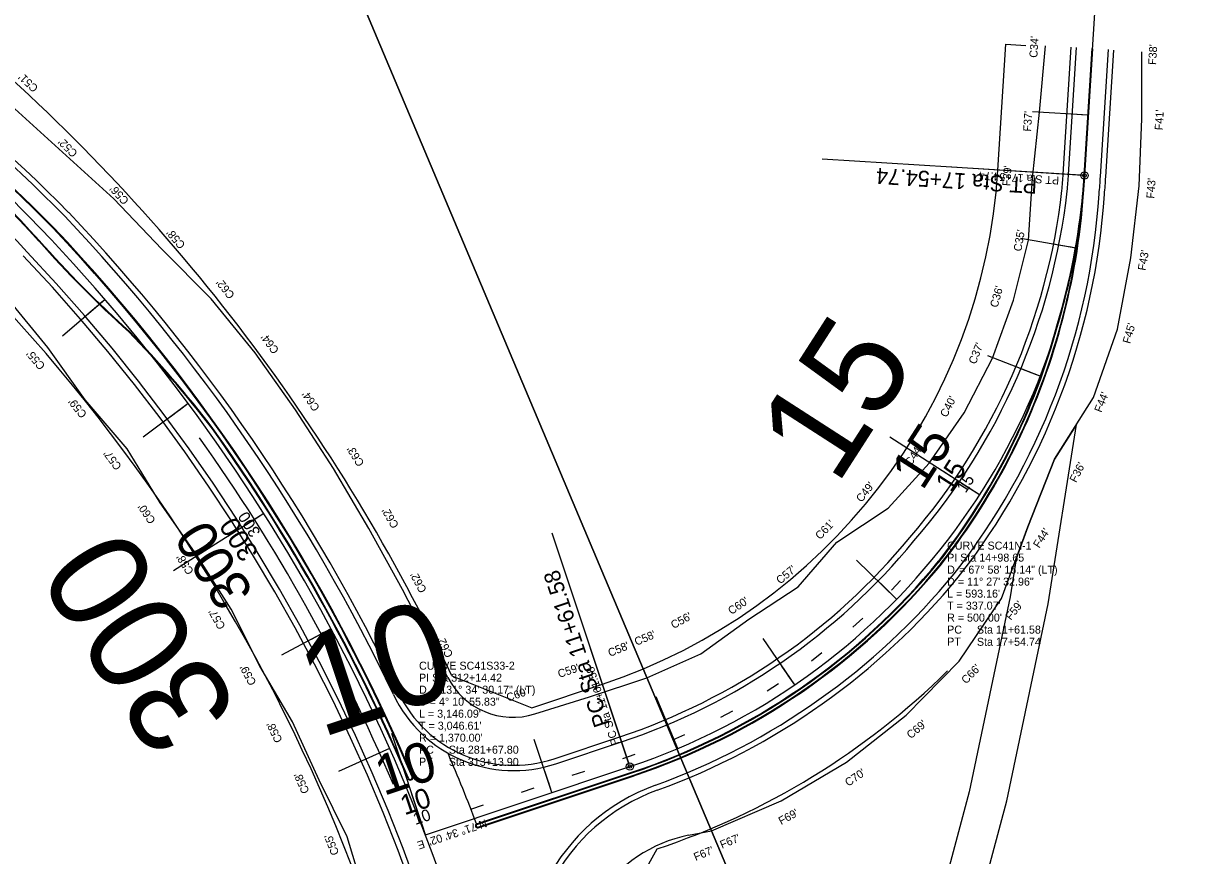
# Model space of a CAD drawing. Extents: x 2358865 to 2362945, y 393485 to 404880.
# Drawn here: x 2361585 to 2362454, y 401432 to 402057 of the extents above; entities that cross this region are included whole.
import ezdxf

# ---------------------------------------------------------------- set-up
doc = ezdxf.new("R2010")
doc.units = 0
for name, color, linetype in [('CL', 7, 'Continuous'), ('Level 11', 7, 'Continuous'), ('Level 19', 7, 'Continuous'), ('Level 21', 7, 'Continuous'), ('Level 22', 7, 'Continuous'), ('Level 25', 7, 'Continuous'), ('Level 27', 7, 'Continuous'), ('Level 28', 7, 'Continuous'), ('Level 30', 7, 'Continuous'), ('Level 33', 7, 'Continuous'), ('Level 35', 7, 'Continuous'), ('Level 36', 7, 'Continuous'), ('Level 37', 7, 'Continuous'), ('Level 39', 7, 'Continuous'), ('Level 41', 7, 'Continuous'), ('Level 48', 7, 'Continuous'), ('Level 50', 7, 'Continuous'), ('Level 51', 7, 'Continuous'), ('Level 52', 7, 'Continuous'), ('Level 53', 7, 'Continuous'), ('Level 61', 7, 'Continuous'), ('Level 63', 7, 'Continuous')]:
    doc.layers.add(name, color=color, linetype=linetype)

msp = doc.modelspace()

# ---------------------------------------------------------------- linework, layer by layer
at = {"layer": 'CL'}
for p, q in [((2362381, 401942.38), (2362564.78, 404866.59)), ((2361886.79, 401448.3), (2362040.08, 401499.39))]:
    msp.add_line(p, q, dxfattribs=at)
for centre, radius, start, end in [((2360608.55, 400955.34), 1370, 315.75191, 87.32696), ((2361881.98, 401973.74), 500, 288.43269, 356.40384)]:
    msp.add_arc(centre, radius, start, end, dxfattribs=at)
at = {"layer": 'Level 11'}
for p, q in [((2362365.03, 401943.38), (2362371.01, 402038.45)), ((2362396.97, 401941.37), (2362402.94, 402036.45)), ((2361983.42, 401505.28), (2362032.65, 401521.68))]:
    msp.add_line(p, q, dxfattribs=at)
for centre, radius, start, end in [((2360631.17, 400937.8), 1389.46, 44.67453, 59.73673), ((2361881.98, 401973.74), 484, 354.94405, 356.40384), ((2361881.98, 401973.74), 516, 354.94405, 356.40384), ((2361887.08, 401985.35), 480.09, 319.11516, 353.52136), ((2361877.46, 401961.88), 519.6, 321.89792, 356.30055), ((2360608.55, 400955.34), 1393.5, 25.49016, 43.50459), ((2360608.55, 400955.34), 1346.5, 319.72072, 43.50459), ((2361881.98, 401973.74), 476.5, 288.43269, 320.57265), ((2361881.98, 401973.74), 523.5, 289.95493, 320.57169), ((2361953.07, 401596.35), 96, 205.49016, 288.43269), ((2362110.47, 401344.43), 146, 109.95493, 194.52415)]:
    msp.add_arc(centre, radius, start, end, dxfattribs=at)
at = {"layer": 'Level 19'}
for p, q in [((2362369.02, 401943.13), (2362375, 402038.2)), ((2362392.98, 401941.62), (2362398.95, 402036.7)), ((2361984.68, 401501.48), (2362033.91, 401517.89))]:
    msp.add_line(p, q, dxfattribs=at)
for centre, radius, start, end in [((2360631.17, 400937.8), 1385.46, 44.67453, 59.73673), ((2360586.69, 400973.8), 1353.95, 42.30084, 57.36334), ((2361881.98, 401973.74), 488, 354.94405, 356.40384), ((2361881.98, 401973.74), 512, 354.94405, 356.40384), ((2361887.08, 401985.35), 484.09, 319.12118, 353.52136), ((2361877.46, 401961.88), 515.6, 321.90306, 356.30055), ((2360608.55, 400955.34), 1389.5, 25.49016, 43.50459), ((2360608.55, 400955.34), 1350.5, 319.72072, 43.50459), ((2361881.98, 401973.74), 480.5, 288.43269, 320.56658), ((2361881.98, 401973.74), 519.5, 289.95493, 320.56658), ((2361953.07, 401596.35), 100, 205.49016, 288.43269), ((2362110.47, 401344.43), 150, 109.95493, 194.52415)]:
    msp.add_arc(centre, radius, start, end, dxfattribs=at)
at = {"layer": 'Level 25'}
for p, q in [((2362383.84, 401987.55), (2362378.85, 401987.86)), ((2362374.59, 401888.04), (2362369.66, 401888.9)), ((2361646.55, 401849.47), (2361642.76, 401846.21)), ((2362347.74, 401791.88), (2362343.08, 401793.7)), ((2361708.99, 401771.39), (2361704.97, 401768.41)), ((2362302.33, 401702.98), (2362295.6, 401707.31)), ((2361765.57, 401688.96), (2361758.82, 401684.68)), ((2362240.16, 401624.87), (2362236.58, 401628.35)), ((2361815.99, 401602.63), (2361811.59, 401600.27)), ((2362163.71, 401560.66), (2362160.89, 401564.79)), ((2362076.03, 401512.93), (2362074.09, 401517.53)), ((2361859.98, 401512.85), (2361855.42, 401510.82)), ((2361981.66, 401479.92), (2361980.08, 401484.66)), ((2361886.79, 401448.3), (2361884.26, 401455.89))]:
    msp.add_line(p, q, dxfattribs=at)
at = {"layer": 'Level 27'}
for p, q in [((2362316.13, 401946.45), (2362322.06, 402040.82)), ((2362322.06, 402040.82), (2362337.03, 402039.87)), ((2361906.52, 401567.32), (2361966.52, 401543.39)), ((2361966.52, 401543.39), (2362019.53, 401561.05)), ((2362002.99, 401334.23), (2362060.53, 401437.69)), ((2362060.53, 401437.69), (2362060.63, 401437.72))]:
    msp.add_line(p, q, dxfattribs=at)
for centre, radius, start, end in [((2360608.55, 400955.34), 1310, 18.31889, 61.65271), ((2360608.55, 400955.34), 1435, 25.24354, 49.10619), ((2361881.98, 401973.74), 435, 288.43269, 356.40384), ((2361881.98, 401973.74), 565, 288.43269, 314.55429)]:
    msp.add_arc(centre, radius, start, end, dxfattribs=at)
at = {"layer": 'Level 28'}
for p, q in [((2362379.75, 401942.45), (2362281.47, 401948.63)), ((2362039.68, 401500.58), (2362010.58, 401587.89))]:
    msp.add_line(p, q, dxfattribs=at)
for centre in [(2362381, 401942.38), (2362040.08, 401499.39)]:
    msp.add_circle(centre, 1.25, dxfattribs=at)
at = {"layer": 'Level 30'}
for p, q in [((2362383.84, 401987.55), (2362375.36, 401988.08)), ((2362374.59, 401888.04), (2362366.21, 401889.5)), ((2361646.55, 401849.47), (2361640.11, 401843.92)), ((2362347.74, 401791.88), (2362339.82, 401794.98)), ((2361708.99, 401771.39), (2361702.16, 401766.33)), ((2362302.33, 401702.98), (2362288.88, 401711.64)), ((2361765.57, 401688.96), (2361752.06, 401680.4)), ((2362240.16, 401624.87), (2362234.07, 401630.8)), ((2361815.99, 401602.63), (2361808.5, 401598.62)), ((2362163.71, 401560.66), (2362158.92, 401567.68)), ((2362076.03, 401512.93), (2362072.73, 401520.76)), ((2361859.98, 401512.85), (2361852.22, 401509.39)), ((2361981.66, 401479.92), (2361978.97, 401487.98)), ((2361886.79, 401448.3), (2361881.73, 401463.48))]:
    msp.add_line(p, q, dxfattribs=at)
at = {"layer": 'Level 33'}
for p, q in [((2362378.3, 401942.55), (2362184.24, 401954.74)), ((2362039.23, 401501.95), (2361981.81, 401674.21))]:
    msp.add_line(p, q, dxfattribs=at)
for centre in [(2362381, 401942.38), (2362040.08, 401499.39)]:
    msp.add_circle(centre, 2.7, dxfattribs=at)
at = {"layer": 'Level 35'}
msp.add_arc((2360618.78, 400958.7), 1398, 20.85338, 23.1961, dxfattribs=at)
at = {"layer": 'Level 36'}
for p, q in [((2362236.18, 401631.54), (2362243.06, 401638.8)), ((2362207.25, 401603.93), (2362214.7, 401610.61)), ((2362176.18, 401578.76), (2362184.14, 401584.82)), ((2362143.17, 401556.2), (2362151.59, 401561.59)), ((2362108.43, 401536.38), (2362117.26, 401541.07)), ((2362072.2, 401519.45), (2362081.39, 401523.41)), ((2362034.72, 401505.51), (2362044.19, 401508.72)), ((2361996.77, 401492.86), (2362006.26, 401496.02)), ((2361958.83, 401480.21), (2361968.31, 401483.38)), ((2361920.88, 401467.57), (2361930.37, 401470.73))]:
    msp.add_line(p, q, dxfattribs=at)
msp.add_arc((2360608.01, 400954.78), 1362.5, 22.94087, 35.48747, dxfattribs=at)
at = {"layer": 'Level 37'}
for p, q in [((2362380.75, 401942.39), (2362386.72, 402037.46)), ((2362381.25, 401942.36), (2362387.22, 402037.43)), ((2361925.2, 401456.36), (2362041.5, 401495.12)), ((2361925.36, 401455.89), (2362041.66, 401494.65)), ((2361926.11, 401454.03), (2362042.29, 401492.75)), ((2361926.27, 401453.55), (2362042.45, 401492.27))]:
    msp.add_line(p, q, dxfattribs=at)
for centre, radius, start, end in [((2360586.69, 400973.8), 1365.95, 42.30084, 56.86254), ((2360631.17, 400937.8), 1373.46, 44.67453, 59.2385), ((2360586.69, 400973.8), 1366.45, 42.30084, 56.3574), ((2360631.17, 400937.8), 1372.96, 44.67453, 58.73575), ((2361881.98, 401973.74), 499.75, 354.9005, 356.40384), ((2361881.98, 401973.74), 500.25, 354.9005, 356.40384), ((2361882.23, 401975.03), 499.62, 343.29164, 354.75087), ((2361880.12, 401962.68), 501.24, 344.7134, 356.17826), ((2361882.23, 401975.03), 500.12, 343.29164, 352.45531), ((2361880.12, 401962.68), 500.74, 344.7134, 353.88728), ((2360608.55, 400955.34), 1377, 22.92825, 43.50459), ((2360608.55, 400955.34), 1377.5, 22.92825, 43.50459), ((2362225.76, 402450.09), 840, 221.51699, 228.05535), ((2362225.76, 402450.09), 839.5, 221.51699, 228.05535), ((2361877.46, 401961.88), 500.6, 321.90306, 344.88936), ((2361877.46, 401961.88), 501.1, 321.90306, 344.88936), ((2361877.46, 401961.88), 503.1, 321.90306, 344.88073), ((2361877.46, 401961.88), 503.6, 321.90306, 344.88073), ((2361060.46, 401241.36), 840, 37.47579, 44.04044), ((2361060.46, 401241.36), 840.5, 37.47579, 44.04044), ((2360608.55, 400955.34), 1373.5, 22.92825, 35.47481), ((2360608.55, 400955.34), 1374, 22.92825, 35.47481), ((2361881.98, 401973.74), 504.5, 288.43269, 320.56658), ((2361881.98, 401973.74), 505, 288.43269, 320.56658), ((2361881.98, 401973.74), 507, 288.43269, 320.56658), ((2361881.98, 401973.74), 507.5, 288.43269, 320.56658), ((2361875.38, 401491.2), 2, 202.94087, 22.94087), ((2361875.38, 401491.2), 1.5, 202.94087, 22.94087), ((2361925.8, 401454.98), 1.5, 108.43269, 288.43269), ((2361925.8, 401454.98), 1, 108.43269, 288.43269)]:
    msp.add_arc(centre, radius, start, end, dxfattribs=at)
at = {"layer": 'Level 39'}
for p, q in [((2362383.84, 401987.55), (2362366.87, 401988.61)), ((2362374.59, 401888.04), (2362357.84, 401890.96)), ((2361646.55, 401849.47), (2361633.67, 401838.37)), ((2362347.74, 401791.88), (2362331.91, 401798.07)), ((2361708.99, 401771.39), (2361695.33, 401761.26)), ((2362302.33, 401702.98), (2362275.43, 401720.31)), ((2361765.57, 401688.96), (2361738.55, 401671.83)), ((2362240.16, 401624.87), (2362227.98, 401636.73)), ((2361815.99, 401602.63), (2361801.01, 401594.6)), ((2362163.71, 401560.66), (2362154.13, 401574.71)), ((2362076.03, 401512.93), (2362069.43, 401528.59)), ((2361859.98, 401512.85), (2361844.45, 401505.93)), ((2361981.66, 401479.92), (2361976.28, 401496.05)), ((2361886.79, 401448.3), (2361876.67, 401478.66))]:
    msp.add_line(p, q, dxfattribs=at)
at = {"layer": 'Level 41'}
for p, q in [((2362383.84, 401987.55), (2362341.92, 401990.18)), ((2362374.59, 401888.04), (2362333.21, 401895.24)), ((2361646.55, 401849.47), (2361614.72, 401822.06)), ((2362347.74, 401791.88), (2362308.62, 401807.16)), ((2361708.99, 401771.39), (2361675.25, 401746.37)), ((2362302.33, 401702.98), (2362235.07, 401746.3)), ((2361765.57, 401688.96), (2361698.01, 401646.12)), ((2362240.16, 401624.87), (2362210.07, 401654.17)), ((2361815.99, 401602.63), (2361778.98, 401582.79)), ((2362163.71, 401560.66), (2362140.04, 401595.36)), ((2362076.03, 401512.93), (2362059.73, 401551.63)), ((2361886.79, 401448.3), (2361861.49, 401524.2)), ((2361981.66, 401479.92), (2361968.38, 401519.76)), ((2361859.98, 401512.85), (2361821.62, 401495.76))]:
    msp.add_line(p, q, dxfattribs=at)
at = {"layer": 'Level 48'}
for centre, radius, start, end in [((2360631.17, 400937.8), 1372.96, 44.67986, 58.73575), ((2360586.69, 400973.8), 1366.45, 42.3191, 56.3574), ((2360608.55, 400955.34), 1377, 22.92827, 43.49928), ((2362225.76, 402450.09), 839.5, 221.504, 228.05655), ((2361060.46, 401241.36), 840.5, 37.4752, 44.04163), ((2360608.55, 400955.34), 1374, 22.92827, 35.47518), ((2361875.38, 401491.2), 1.5, 202.92827, 22.92827)]:
    msp.add_arc(centre, radius, start, end, dxfattribs=at)
at = {"layer": 'Level 50'}
for p, q in [((2361614.55, 401959.8), (2361576.27, 401994.85)), ((2361653.17, 401924.84), (2361614.55, 401959.8)), ((2361689.05, 401887.07), (2361653.17, 401924.84)), ((2362327.82, 401848.99), (2362339.03, 401894.04)), ((2361726.02, 401849.94), (2361689.05, 401887.07)), ((2361603.65, 401813.42), (2361573.29, 401850.7)), ((2361759.05, 401809.38), (2361726.02, 401849.94)), ((2362312.08, 401805.42), (2362327.82, 401848.99)), ((2361631.62, 401774.36), (2361603.65, 401813.42)), ((2361789.47, 401766.81), (2361759.05, 401809.38)), ((2362290.83, 401764.41), (2362312.08, 401805.42)), ((2361663.23, 401737.46), (2361631.62, 401774.36)), ((2361817.83, 401722.85), (2361789.47, 401766.81)), ((2362264.49, 401726.74), (2362290.83, 401764.41)), ((2361687.93, 401697.02), (2361663.23, 401737.46)), ((2362233.7, 401693.07), (2362264.49, 401726.74)), ((2361844.27, 401677.75), (2361817.83, 401722.85)), ((2361715.34, 401657.78), (2361687.93, 401697.02)), ((2362195.32, 401667.65), (2362233.7, 401693.07)), ((2361869.61, 401632.04), (2361844.27, 401677.75)), ((2362166.38, 401634.04), (2362195.32, 401667.65)), ((2361741.08, 401617.4), (2361715.34, 401657.78)), ((2361903.56, 401566.12), (2361869.61, 401632.04)), ((2362129.38, 401609.74), (2362166.38, 401634.04)), ((2361762.73, 401574.66), (2361741.08, 401617.4)), ((2362093.43, 401583.82), (2362129.38, 401609.74)), ((2362052.92, 401565.87), (2362093.43, 401583.82)), ((2362247.29, 401537.84), (2362287.02, 401578.45)), ((2361787.13, 401532.82), (2361762.73, 401574.66)), ((2362009.73, 401551.57), (2362052.92, 401565.87)), ((2361968.85, 401538.81), (2362009.73, 401551.57)), ((2362202.52, 401502.65), (2362247.29, 401537.84)), ((2361807.07, 401489.28), (2361787.13, 401532.82)), ((2361828.08, 401446.6), (2361807.07, 401489.28)), ((2361842.33, 401400.71), (2361828.08, 401446.6))]:
    msp.add_line(p, q, dxfattribs=at)
msp.add_arc((2361952.46, 401591.31), 55, 207.24943, 287.34074, dxfattribs=at)
at = {"layer": 'Level 51'}
for p, q in [((2362424.07, 401984.94), (2362424.08, 402035.04)), ((2362341.96, 401940.45), (2362347.35, 401989.84)), ((2362422.12, 401934.61), (2362424.07, 401984.94)), ((2362415.69, 401880.75), (2362422.12, 401934.61)), ((2362405.7, 401827.3), (2362415.69, 401880.75)), ((2362387.85, 401775.9), (2362405.7, 401827.3)), ((2362358.56, 401729.87), (2362387.85, 401775.9)), ((2362338.58, 401679.09), (2362358.56, 401729.87)), ((2362318.79, 401625.43), (2362338.58, 401679.09)), ((2362101.26, 401451.3), (2362153.49, 401473.68)), ((2362084.1, 401447.87), (2362101.26, 401451.3))]:
    msp.add_line(p, q, dxfattribs=at)
at = {"layer": 'Level 52'}
for p, q in [((2362347.35, 401989.84), (2362351.76, 402039.62)), ((2362339.03, 401894.04), (2362341.96, 401940.45)), ((2362287.02, 401578.45), (2362318.79, 401625.43)), ((2362153.49, 401473.68), (2362202.52, 401502.65))]:
    msp.add_line(p, q, dxfattribs=at)
msp.add_arc((2362104.67, 401344.91), 105, 101.29963, 192.42448, dxfattribs=at)
at = {"layer": 'Level 61'}
for p, q in [((2362353.8, 401621.34), (2362374.97, 401755.66)), ((2362374.97, 401755.66), (2362358.56, 401729.87)), ((2362358.56, 401729.87), (2362338.58, 401679.09)), ((2362338.58, 401679.09), (2362329.77, 401655.2)), ((2362329.77, 401655.2), (2362325.27, 401626.59)), ((2362325.27, 401626.59), (2362294.45, 401480.49)), ((2362322.67, 401473.76), (2362353.8, 401621.34)), ((2362294.45, 401480.49), (2362256.09, 401336.32)), ((2362283.92, 401328.15), (2362322.67, 401473.76))]:
    msp.add_line(p, q, dxfattribs=at)
at = {"layer": 'Level 63'}
for points in [[(2362461.5, 402543.91), (2361764.38, 402249.82), (2362269.69, 401052.04), (2362944.62, 401336.78)], [(2361426.35, 402053.51), (2361146.52, 401677.8), (2361146.52, 401677.8), (2361497.41, 400807.35), (2361959.57, 400730.75), (2361959.57, 400730.75), (2362107.55, 400706.22), (2362344.68, 400666.91), (2362325.19, 400877.16), (2362269.69, 401052.04), (2361764.38, 402249.82), (2361644.31, 402346.15), (2361515.95, 402173.81)]]:
    msp.add_lwpolyline(points, close=True, dxfattribs=at)

# ---------------------------------------------------------------- texts
at = {"layer": 'Level 21'}
msp.add_text('N 71%%d 34\' 02" E', height=6, rotation=198.43269, dxfattribs=at).set_placement((2361931.63, 401460.02))
at = {"layer": 'Level 22'}
for s, p in [('CURVE SC41N-1', (2362278, 401662)), ('PI Sta 14+98.65', (2362278, 401653)), ('D', (2362278, 401644)), ('= 67%%d 58\' 16.14" (LT)', (2362287, 401644)), ('D = 11%%d 27\' 32.96"', (2362278, 401635.01)), ("L = 593.16'", (2362278, 401626.02)), ("T = 337.07'", (2362278, 401617.02)), ("R = 500.00'", (2362278, 401608.03)), ('PC', (2362278, 401599.03)), ('Sta 11+61.58', (2362300.33, 401599.05)), ('PT', (2362278, 401590.04)), ('Sta 17+54.74', (2362300.33, 401589.91)), ('CURVE SC41S33-2', (2361882, 401572)), ('PI Sta 312+14.42', (2361882, 401563)), ('D', (2361882, 401554)), ('= 131%%d 34\' 30.17" (LT)', (2361891, 401554)), ('D = 4%%d 10\' 55.83"', (2361882, 401545.01)), ("L = 3,146.09'", (2361882, 401536.02)), ("T = 3,046.61'", (2361882, 401527.02)), ("R = 1,370.00'", (2361882, 401518.03)), ('PC', (2361882, 401509.03)), ('Sta 281+67.80', (2361904.33, 401509.05)), ('PT', (2361882, 401500.04)), ('Sta 313+13.90', (2361904.33, 401499.91))]:
    msp.add_text(s, height=6, dxfattribs=at).set_placement(p)
at = {"layer": 'Level 25'}
for s, rotation, p in [('15', 57.21289, (2362291.88, 401703.85)), ('300', 122.3775, (2361763.52, 401674.93)), ('10', 18.43269, (2361879.29, 401455.55))]:
    msp.add_text(s, height=8.75, rotation=rotation, dxfattribs=at).set_placement(p)
at = {"layer": 'Level 28'}
for s, rotation, p in [('PT Sta 17+54.74', 176.40384, (2362362.16, 401941.56)), ('PC Sta 11+61.58', 108.43269, (2362032.25, 401516.55))]:
    msp.add_text(s, height=6, rotation=rotation, dxfattribs=at).set_placement(p)
at = {"layer": 'Level 30'}
for s, rotation, p in [('15', 57.21289, (2362280.89, 401704.23)), ('300', 122.3775, (2361762.11, 401659.5)), ('10', 18.43269, (2361871.07, 401462.77))]:
    msp.add_text(s, height=15, rotation=rotation, dxfattribs=at).set_placement(p)
at = {"layer": 'Level 33'}
for s, rotation, p in [('PT Sta 17+54.74', 176.40384, (2362345.82, 401940.58)), ('PC Sta 11+61.58', 108.43269, (2362025.22, 401531.33))]:
    msp.add_text(s, height=12, rotation=rotation, dxfattribs=at).set_placement(p)
at = {"layer": 'Level 39'}
for s, rotation, p in [('15', 57.21289, (2362259.45, 401705.48)), ('300', 122.3775, (2361758.65, 401630.03)), ('10', 18.43269, (2361855.36, 401477.25))]:
    msp.add_text(s, height=30, rotation=rotation, dxfattribs=at).set_placement(p)
at = {"layer": 'Level 41'}
for s, rotation, p in [('15', 57.21289, (2362195.07, 401709.12)), ('300', 122.3775, (2361748.44, 401541.38)), ('10', 18.43269, (2361808.07, 401520.62))]:
    msp.add_text(s, height=75, rotation=rotation, dxfattribs=at).set_placement(p)
at = {"layer": 'Level 53'}
for s, rotation, p in [("C34'", 86.40384, (2362345.61, 402030.47)), ("F38'", 86.40384, (2362434.68, 402025.14)), ("C51'", 137.04857, (2361596.95, 402008.55)), ("F37'", 86.40384, (2362340.95, 401975.17)), ("F41'", 86.40384, (2362439.55, 401976.18)), ("C52'", 134.95629, (2361626.43, 401959.62)), ("F39'", 85.85299, (2362325.33, 401934.29)), ("F43'", 85.85299, (2362433.32, 401924.93)), ("C56'", 132.86401, (2361664.87, 401923.94)), ("C58'", 130.77173, (2361707.17, 401890.56)), ("C35'", 80.11258, (2362333.59, 401885.17)), ("F43'", 80.11258, (2362426.77, 401870.79)), ("C62'", 128.67945, (2361744.16, 401852.88)), ("C36'", 74.37274, (2362315.75, 401842.97)), ("F45'", 74.37274, (2362415.23, 401815.93)), ("C64'", 126.58718, (2361777.37, 401811.54)), ("C37'", 68.63358, (2362299.4, 401800.46)), ("C55'", 130.77173, (2361602.08, 401799.93)), ("C64'", 124.49492, (2361807.86, 401768.3)), ("F44'", 68.63358, (2362393.7, 401764.33)), ("C59'", 128.67945, (2361633.33, 401763.57)), ("C40'", 62.89518, (2362277.68, 401760.66)), ("C63'", 122.40267, (2361841.25, 401726.73)), ("C44'", 57.15764, (2362250.95, 401724.21)), ("C57'", 126.58718, (2361659.36, 401724.37)), ("F36'", 62.89518, (2362374.73, 401711.78)), ("C49'", 51.42104, (2362213.79, 401697)), ("C60'", 124.49492, (2361684.82, 401683.9)), ("C62'", 120.31042, (2361867.11, 401680.19)), ("C61'", 45.68545, (2362182.73, 401669.08)), ("F44'", 57.15764, (2362347.04, 401662.69)), ("C58'", 122.40267, (2361713.36, 401645.68)), ("C57'", 39.95092, (2362152.88, 401635.78)), ("C62'", 118.21819, (2361887.99, 401631.63)), ("C60'", 34.21752, (2362116.27, 401612.92)), ("F59'", 51.42104, (2362325.84, 401608.6)), ("C57'", 120.31042, (2361737.11, 401604.38)), ("C56'", 28.48526, (2362072.84, 401602.44)), ("C62'", 116.12597, (2361907.78, 401582.92)), ("C58'", 22.75418, (2362045.04, 401589.88)), ("C58'", 22.75418, (2362025.19, 401581.51)), ("C59'", 118.21819, (2361760.24, 401562.2)), ("C59'", 18.43269, (2361987.22, 401565.8)), ("C66'", 45.68545, (2362292.25, 401560.9)), ("C60'", 18.43269, (2361948.67, 401548.04)), ("C58'", 116.12597, (2361779.83, 401519.04)), ("C69'", 39.95092, (2362250.73, 401519.85)), ("C58'", 114.03377, (2361800, 401480.7)), ("C70'", 34.21752, (2362203.88, 401484.22)), ("F69'", 28.48526, (2362153.54, 401455.5)), ("F69'", 28.48526, (2362153.54, 401455.5)), ("F69'", 28.48526, (2362153.54, 401455.5)), ("F67'", 22.75418, (2362109.2, 401437.73)), ("C55'", 111.94158, (2361822.24, 401434.34)), ("F67'", 22.75418, (2362089.47, 401428.56))]:
    msp.add_text(s, height=6, rotation=rotation, dxfattribs=at).set_placement(p)

doc.saveas('drawing.dxf')
